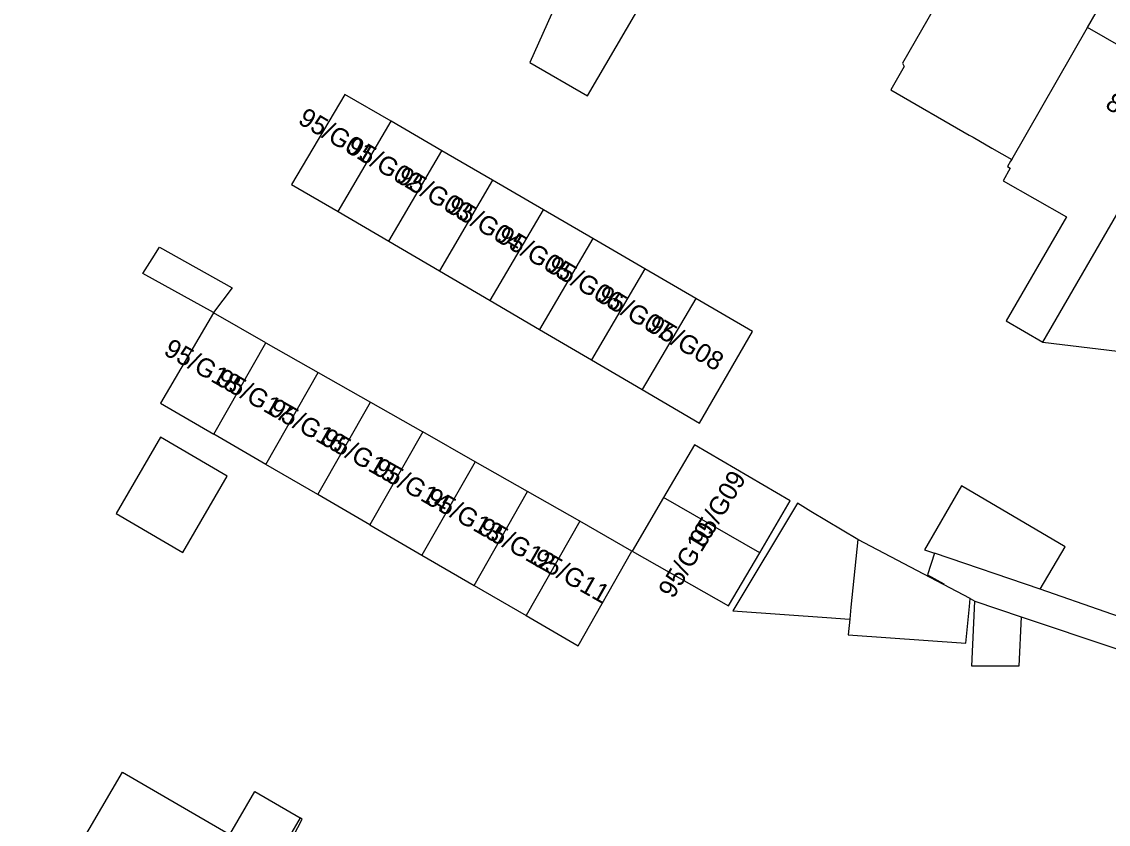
# Model space of a CAD drawing. Extents: x 160356 to 161355, y 381727 to 382845.
# Drawn here: x 160821.5 to 160879.6, y 382168.2 to 382211.2 of the extents above; entities that cross this region are included whole.
import ezdxf

# ---------------------------------------------------------------- set-up
doc = ezdxf.new("R2010")
doc.units = 0
for name, color, linetype in [('IMGEO_Pand', 7, 'Continuous'), ('IMGEO_Pand_nummerreeks', 7, 'Continuous'), ('IMGEO_Voetpad_open', 7, 'Continuous')]:
    doc.layers.add(name, color=color, linetype=linetype)

msp = doc.modelspace()

# ---------------------------------------------------------------- linework, layer by layer
at = {"layer": 'IMGEO_Pand'}
for points in [[(160863.097, 382226.769), (160860.481, 382228.273), (160859.872, 382227.214), (160855.223, 382229.885), (160852.732, 382225.551), (160852.238, 382224.741), (160849.89, 382220.767), (160852.96, 382218.953), (160853.103, 382218.869), (160848.688, 382209.017), (160851.777, 382207.241), (160855.395, 382213.457)], [(160878.533, 382210.905), (160879.469, 382212.531), (160879.625, 382212.802), (160873.752, 382216.181), (160871.75, 382212.699), (160871.008, 382213.126), (160868.629, 382208.989), (160868.73, 382208.813), (160868.006, 382207.555), (160872.206, 382205.141), (160872.41, 382205.023), (160873.42, 382204.442), (160874.478, 382203.834)], [(160874.478, 382203.834), (160878.533, 382210.905)], [(160884.058, 382207.727), (160878.533, 382210.905)], [(160876.147, 382194.046), (160884.058, 382207.727)], [(160841.268, 382205.879), (160838.797, 382207.317), (160835.948, 382202.494), (160838.434, 382201.038)], [(160838.434, 382201.038), (160841.268, 382205.879)], [(160843.986, 382204.298), (160841.268, 382205.879)], [(160841.146, 382199.45), (160843.986, 382204.298)], [(160846.702, 382202.717), (160843.986, 382204.298)], [(160874.478, 382203.834), (160874.42, 382203.732), (160874.252, 382203.449), (160874.405, 382203.361), (160874.018, 382202.688), (160877.417, 382200.759), (160874.184, 382195.184), (160876.147, 382194.046)], [(160846.702, 382202.717), (160843.859, 382197.861)], [(160849.419, 382201.136), (160846.702, 382202.717)], [(160838.434, 382201.038), (160841.146, 382199.45)], [(160846.571, 382196.273), (160849.419, 382201.136)], [(160852.065, 382199.596), (160849.419, 382201.136)], [(160852.065, 382199.596), (160849.213, 382194.726)], [(160854.852, 382197.974), (160852.065, 382199.596)], [(160831.763, 382195.63), (160827.994, 382197.726), (160828.482, 382198.508), (160828.875, 382199.135), (160832.764, 382196.948), (160831.763, 382195.63)], [(160841.146, 382199.45), (160843.859, 382197.861)], [(160843.859, 382197.861), (160846.571, 382196.273)], [(160854.852, 382197.974), (160851.996, 382193.097)], [(160857.569, 382196.393), (160854.852, 382197.974)], [(160876.147, 382194.046), (160883.1, 382193.21), (160885.296, 382197.097)], [(160846.571, 382196.273), (160849.213, 382194.726)], [(160857.569, 382196.393), (160854.709, 382191.508)], [(160854.709, 382191.508), (160857.769, 382189.716), (160860.604, 382194.627), (160857.569, 382196.393)], [(160834.566, 382194.019), (160831.766, 382195.613), (160828.94, 382190.772), (160831.779, 382189.121)], [(160849.213, 382194.726), (160851.996, 382193.097)], [(160831.779, 382189.121), (160834.566, 382194.019)], [(160834.566, 382194.019), (160837.367, 382192.425)], [(160851.996, 382193.097), (160854.709, 382191.508)], [(160834.565, 382187.501), (160837.367, 382192.425)], [(160837.367, 382192.425), (160840.168, 382190.831)], [(160837.351, 382185.882), (160840.168, 382190.831)], [(160840.168, 382190.831), (160842.968, 382189.237)], [(160834.565, 382187.501), (160831.779, 382189.121)], [(160842.968, 382189.237), (160840.137, 382184.262)], [(160845.769, 382187.643), (160842.968, 382189.237)], [(160826.556, 382184.867), (160830.13, 382182.79), (160832.507, 382186.88), (160828.932, 382188.957), (160826.556, 382184.867)], [(160860.997, 382182.761), (160862.631, 382185.55), (160857.506, 382188.553), (160855.855, 382185.736)], [(160837.351, 382185.882), (160834.565, 382187.501)], [(160845.769, 382187.643), (160842.922, 382182.642)], [(160848.569, 382186.05), (160845.769, 382187.643)], [(160876.005, 382180.813), (160877.345, 382183.086), (160871.791, 382186.36), (160869.814, 382182.924), (160870.348, 382182.742)], [(160840.137, 382184.262), (160837.351, 382185.882)], [(160845.708, 382181.023), (160848.569, 382186.05)], [(160851.37, 382184.456), (160848.569, 382186.05)], [(160855.855, 382185.736), (160854.17, 382182.862), (160859.334, 382179.923), (160860.997, 382182.761)], [(160860.997, 382182.761), (160855.855, 382185.736)], [(160866.249, 382183.476), (160863.737, 382184.985), (160863.013, 382185.42), (160859.554, 382179.659), (160864.828, 382179.281), (160865.559, 382179.229), (160865.814, 382179.211)], [(160848.494, 382179.403), (160851.28, 382177.783), (160854.15, 382182.859), (160851.37, 382184.456)], [(160851.37, 382184.456), (160848.494, 382179.403)], [(160840.137, 382184.262), (160842.922, 382182.642)], [(160866.249, 382183.476), (160865.88, 382179.859), (160865.814, 382179.211)], [(160870.824, 382181.077), (160866.249, 382183.476)], [(160876.005, 382180.813), (160870.348, 382182.742)], [(160842.922, 382182.642), (160845.708, 382181.023)], [(160845.708, 382181.023), (160848.494, 382179.403)], [(160872.26, 382180.324), (160870.824, 382181.077)], [(160865.814, 382179.211), (160865.729, 382178.379), (160872.021, 382177.928), (160872.217, 382179.893), (160872.26, 382180.324)], [(160874.985, 382179.347), (160874.858, 382176.699), (160872.354, 382176.699), (160872.515, 382180.176)], [(160872.515, 382180.176), (160874.985, 382179.347)], [(160830.31, 382158.093), (160826.094, 382160.541), (160825.46, 382159.448), (160821.506, 382161.743), (160824.016, 382166.068), (160826.893, 382171.024), (160832.643, 382167.685), (160833.976, 382169.981), (160836.411, 382168.571)], [(160836.411, 382168.571), (160830.31, 382158.093)], [(160844.765, 382164.296), (160842.285, 382165.735), (160841.554, 382164.461), (160836.056, 382167.616), (160836.52, 382168.508), (160836.411, 382168.571)]]:
    msp.add_lwpolyline(points, dxfattribs=at)
at = {"layer": 'IMGEO_Voetpad_open'}
for points in [[(160870.348, 382182.742), (160869.975, 382181.591), (160870.841, 382181.111), (160870.824, 382181.077)], [(160882.966, 382178.401), (160876.005, 382180.813)], [(160872.26, 382180.324), (160872.515, 382180.176)], [(160874.985, 382179.347), (160885.066, 382175.972)]]:
    msp.add_lwpolyline(points, dxfattribs=at)

# ---------------------------------------------------------------- texts
at = {"layer": 'IMGEO_Pand_nummerreeks'}
for s, rotation, p in [('8', 330.09733, (160879.425, 382206.609)), ('95/G01', 329.30092, (160836.228, 382205.796)), ('95/G02', 329.30092, (160838.808, 382204.264)), ('95/G03', 329.30092, (160841.495, 382202.669)), ('95/G04', 329.30092, (160844.176, 382201.077)), ('95/G05', 329.30092, (160846.857, 382199.485)), ('95/G06', 329.30092, (160849.538, 382197.893)), ('95/G07', 329.30092, (160852.219, 382196.301)), ('95/G08', 329.30092, (160854.902, 382194.707)), ('95/G18', 330.36969, (160829.041, 382193.42)), ('95/G17', 330.36969, (160831.843, 382191.826)), ('95/G16', 330.36969, (160834.648, 382190.231)), ('95/G15', 330.36969, (160837.453, 382188.635)), ('95/G14', 330.36969, (160840.258, 382187.04)), ('95/G09', 58.7271, (160858.028, 382183.01)), ('95/G13', 330.36969, (160843.063, 382185.445)), ('95/G12', 330.36969, (160845.862, 382183.852)), ('95/G10', 58.7271, (160856.362, 382180.267)), ('95/G11', 330.36969, (160848.769, 382182.199))]:
    msp.add_text(s, height=1, rotation=rotation, dxfattribs=at).set_placement(p)

doc.saveas('drawing.dxf')
